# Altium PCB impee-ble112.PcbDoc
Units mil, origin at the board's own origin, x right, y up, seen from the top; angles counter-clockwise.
Board outline 2952.76 x 1968.5 mil, 2 copper layers (Top Layer, Bottom Layer); 26 components, 20 nets, 135 pads, 141 vias.
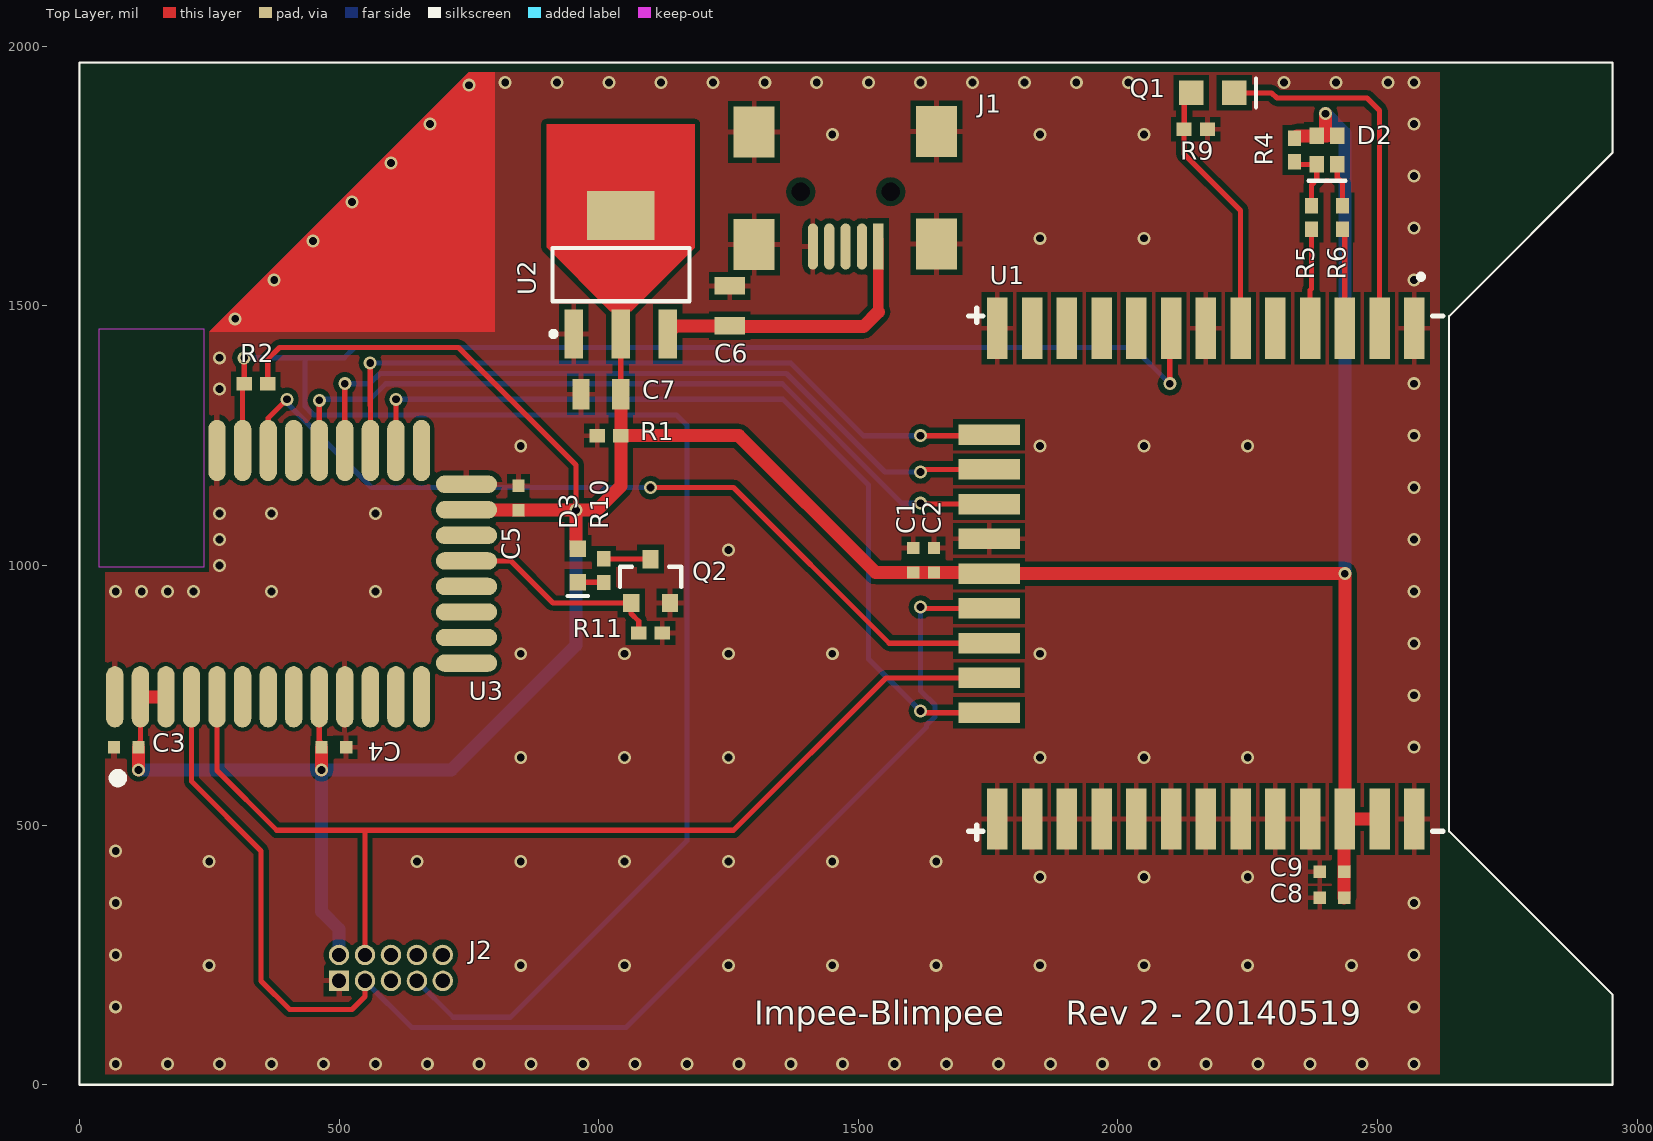
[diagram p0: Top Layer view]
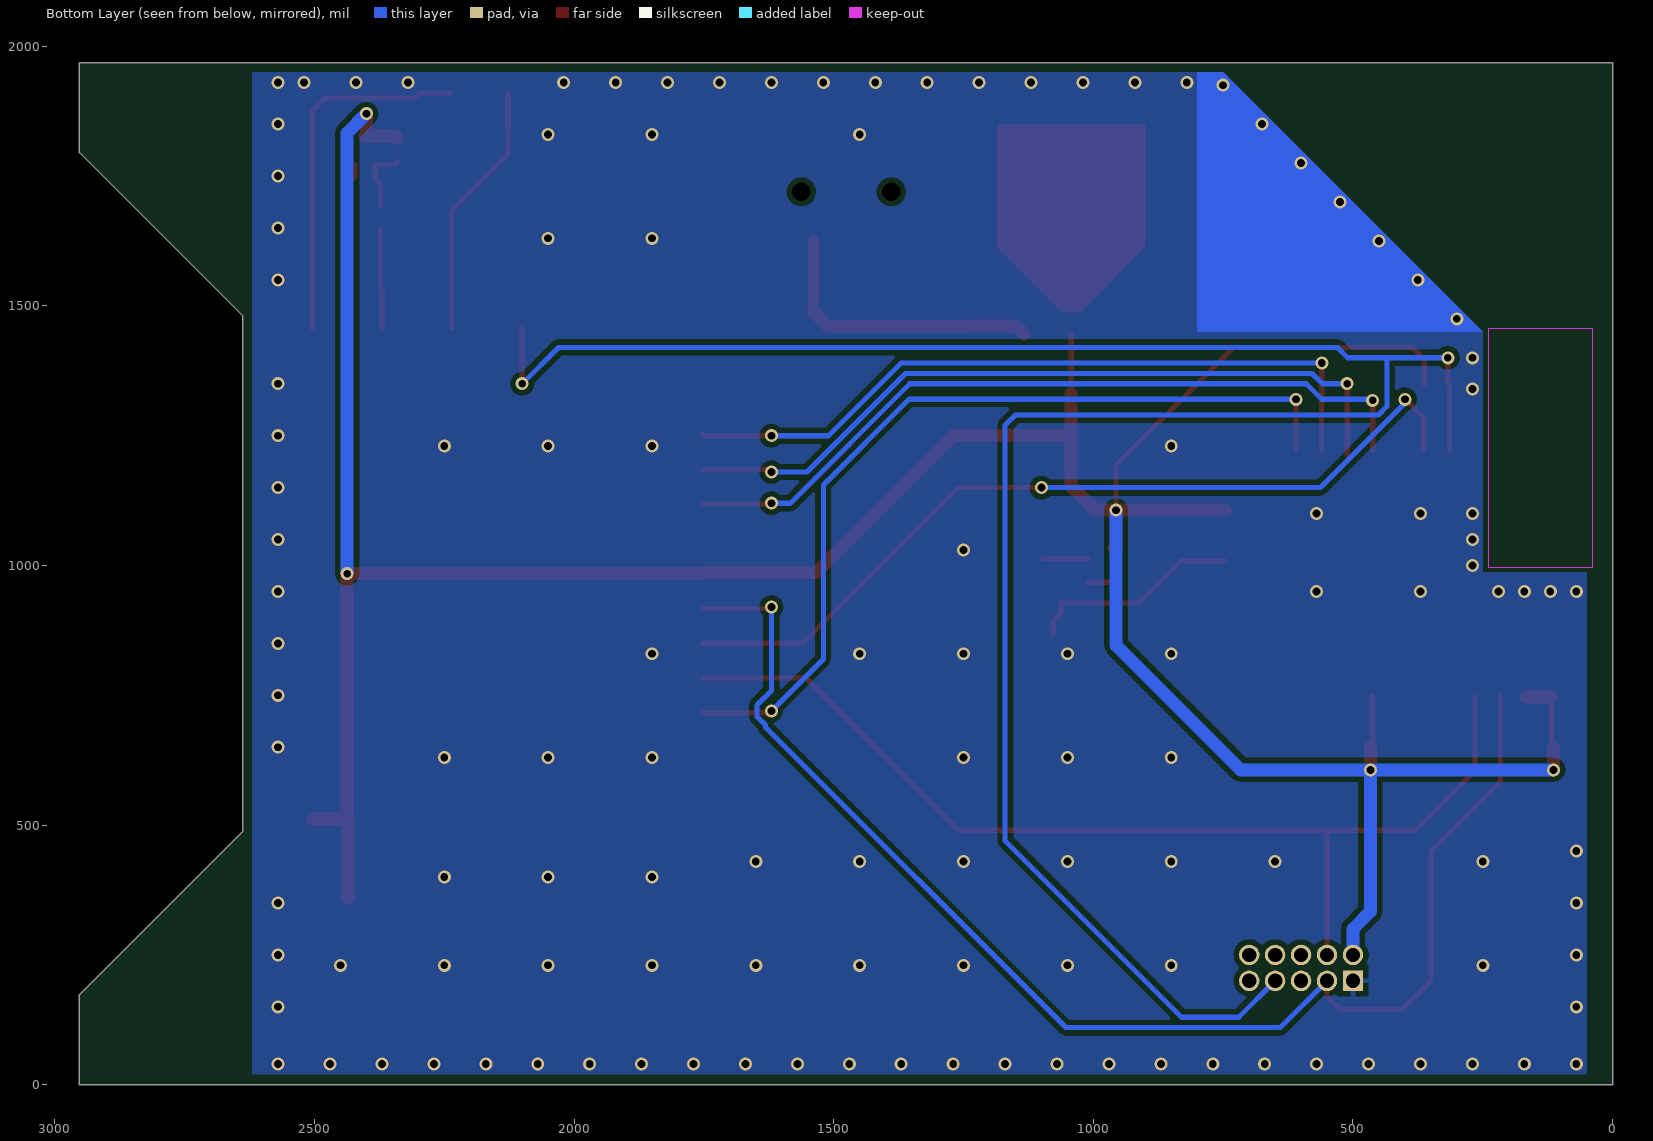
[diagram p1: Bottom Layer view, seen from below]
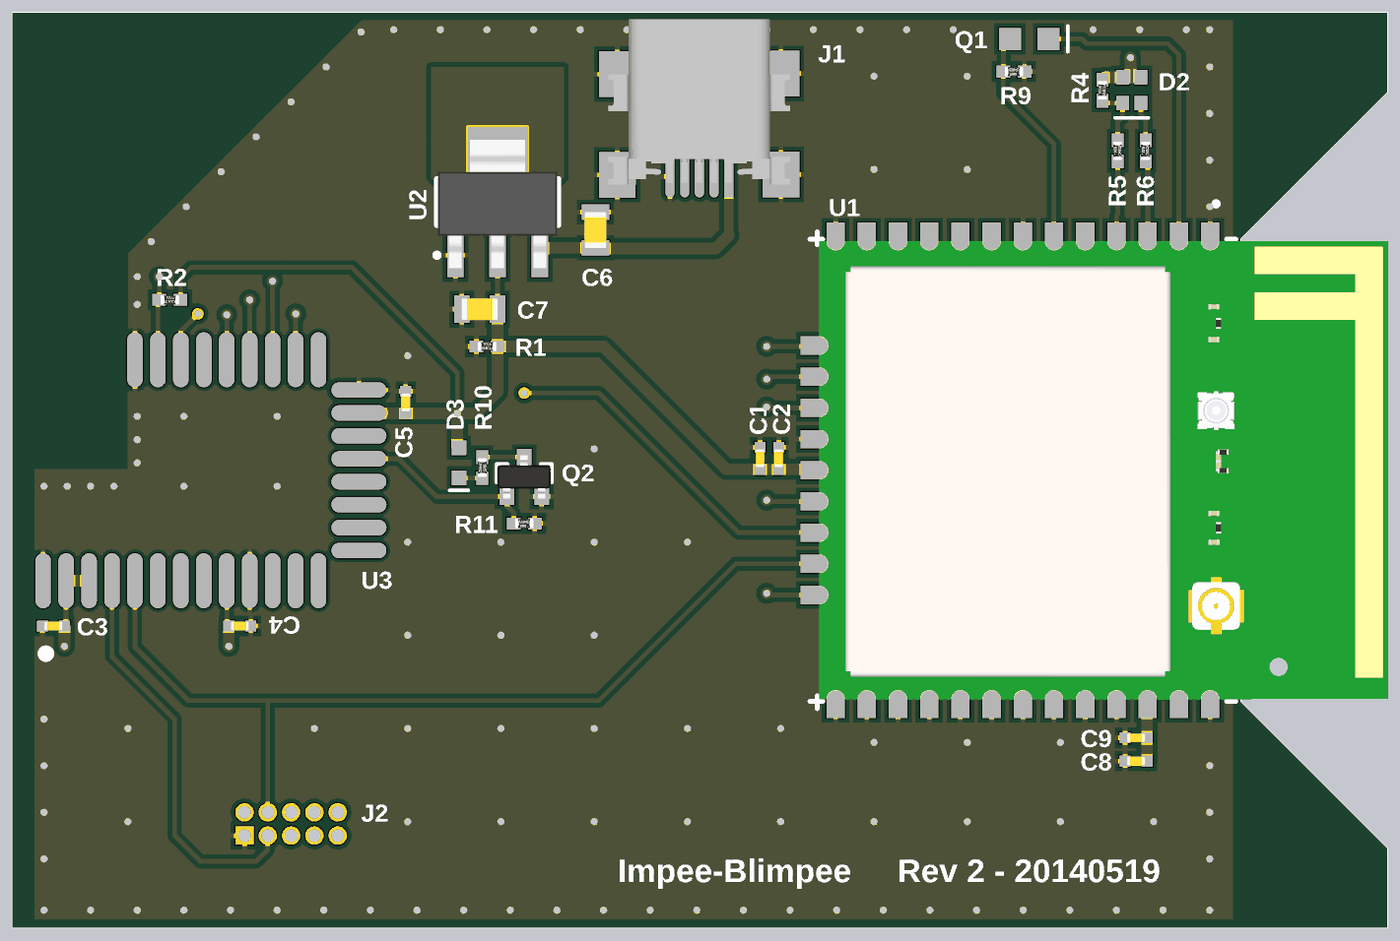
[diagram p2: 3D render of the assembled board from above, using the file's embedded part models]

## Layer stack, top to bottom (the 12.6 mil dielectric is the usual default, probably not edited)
Top Solder: solder mask 0.4, Solder Resist, Dk 3.5
Top Layer: signal copper 1.4
Dielectric 1: dielectric 12.6, FR-4, Dk 4.8
Bottom Layer: signal copper 1.4
Bottom Solder: solder mask 0.4, Solder Resist, Dk 3.5

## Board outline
0,0 0,1968.5 2952.76,1968.5 2952.76,1795.28 2637.8,1480.32 2637.8,488.19 2952.76,173.23 2952.76,0

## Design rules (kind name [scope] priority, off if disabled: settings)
Clearance "PolyRegion Clearance" [IsPad and InComponent('U3') vs IsRegion] p1: gap=8
Clearance [All] p2: gap=10
MinimumSolderMaskSliver [All] p1: minsoldermaskwidth=4
PolygonConnect "Via connect" [isVia] p1: connectstyle=Direct reliefconductorwidth=10 reliefentries=4 polygonreliefangle="90 Angle" airgapwidth=10
PolygonConnect [All] p2: connectstyle=Relief reliefconductorwidth=10 reliefentries=4 polygonreliefangle="90 Angle" airgapwidth=10
RoutingVias [All] p1: holewidth=28 width=50 viastyle="Through Hole" minholewidth=15 minwidth=25 maxholewidth=28 maxwidth=50
SolderMaskExpansion [All] p1: expansion=3
Width [All] p1: maxlimit=25 minlimit=10 preferedwidth=10
28 further rules are at their usual default settings.

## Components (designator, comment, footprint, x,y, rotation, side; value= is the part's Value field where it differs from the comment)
C1 "Ceramic Capacitor" CAPC1005X07N 1605.75,1010 r270 top
C2 "Ceramic Capacitor" CAPC1005X07N 1645.75,1010 r270 top
C3 "Ceramic Capacitor" CAPC1005X07N 90.12,650 r0 top
C4 "Ceramic Capacitor" CAPC1005X07N 490.12,650 r180 top
C5 "Ceramic Capacitor" CAPC1005X07N 845.75,1130 r270 top
C6 "Ceramic Capacitor" CAPC2012X14N 1252.76,1500 r270 top
C7 "Ceramic Capacitor" CAPC2012X14N 1004.37,1330 r0 top
C8 "Ceramic Capacitor" CAPC1005X07N 2412.13,360 r0 top
C9 "Ceramic Capacitor" CAPC1005X07N 2412.13,410 r0 top
D2 "LED Red and Green" LED1616X07N-REDGREEN 2402.76,1800 r90 top
D3 "LED Blue" LED1608X08N-BLUE 960,1000 r90 top
J1 "USB Mini/Micro-B" 4UCON20035 1475.12,1725 r180 top
J2 "Header" HDR127P2X5-N 500,200 r0 top
Q1 "PHOTOTRANSISTOR" PHOTOTRANS2012X13 2182.99,1910.08 r180 top
Q2 "N-Channel MOSFET" SOT95P300X130-3N 1100,970 r90 top
R1 "Resistor" RESC1005X04N 1020.12,1250 r0 top
R2 "Resistor" RESC1005X04N 340,1350 r0 top
R4 "Resistor" RESC1005X04N 2340,1800 r90 top
R5 "Resistor" RESC1005X04N 2372.76,1670 r90 top
R6 "Resistor" RESC1005X04N 2432.76,1670 r90 top
R9 "Resistor" RESC1005X04N 2150,1840 r180 top
R10 "Resistor" RESC1005X04N 1010,990 r270 top
R11 "Resistor" RESC1005X04N 1100,870 r180 top
U1 "imp module" IMP_MODULE 1732.28,1476.38 r270 top locked
U2 "AP1117" SOT230P700X180-4N 1042.76,1560 r90 top
U3 "BLE112" BLE112 389.13,984.25 r90 top

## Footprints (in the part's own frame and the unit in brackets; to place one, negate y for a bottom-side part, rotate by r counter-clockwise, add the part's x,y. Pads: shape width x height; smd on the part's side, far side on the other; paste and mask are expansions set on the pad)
4UCON20035 [mm] "Mini-B USB, Top Mount, Right Angle, SMT"
  rect 0.5x2.25 smd: 1(-1.612,2.813)
  oval 0.5x2.25 smd: 2(-0.812,2.813) 3(-0.012,2.813) 4(0.788,2.813) 5(1.588,2.813)
  round 0 hole 0.9 unplated paste+0 mask+1: H1(-2.213,0.138)
  round 0 hole 0.9 unplated mask+1: H2(2.188,0.138)
  rect 2x2.5 smd: M1(-4.463,2.688) M2(4.463,2.712) M3(-4.463,-2.812) M4(4.463,-2.788)
  body extent -4.95,-5.77 4.95,3.23, height 4.08
BLE112 [mm] "Bluegiga Bluetooth Low Energy Module"
  oval 3x0.85 smd: 1(-6.025,8.15) 2(-6.025,6.9) 3(-6.025,5.65) 4(-6.025,4.4) 5(-6.025,3.15) 6(-6.025,1.9) 7(-6.025,0.65) 8(-6.025,-0.6) 9(-6.025,-1.85) 10(-6.025,-3.1) 11(-6.025,-4.35) 12(-6.025,-5.6) 13(-6.025,-6.85) 22(6.025,-6.85) 23(6.025,-5.6) 24(6.025,-4.35) 25(6.025,-3.1) 26(6.025,-1.85) 27(6.025,-0.6) 28(6.025,0.65) 29(6.025,1.9) 30(6.025,3.15)
  oval 0.85x3 smd: 14(-4.375,-9.05) 15(-3.125,-9.05) 16(-1.875,-9.05) 17(-0.625,-9.05) 18(0.625,-9.05) 19(1.875,-9.05) 20(3.125,-9.05) 21(4.375,-9.05)
  Multi-Layer keep-out region: 0.325,8.9 11.975,8.9 11.975,3.8 0.325,3.8
  silkscreen extent -10.2,7.8 -9.8,8.2, body extent -6.02,-9.05 6.03,9.05, height 2
CAPC1005X07N [mm] "Chip Capacitor, 2-Leads, Body 1.0x0.5mm, IPC Medium Density"
  rect 0.6x0.6 smd: 1(-0.6,0) 2(0.6,0)
  body extent -0.5,-0.25 0.5,0.25, height 0.6
CAPC2012X14N [mm] "Chip Capacitor, 2-Leads, Body 2.0x1.3mm, IPC Medium Density"
  rect 0.85x1.5 smd: 1(-0.975,0) 2(0.975,0)
  body extent -1,-0.6 1,0.6, height 1.4
HDR127P2X5-N [mm] "HDR, 1.27mm Pitch, 2x5-Pin"
  rect 1x1 hole 0.7: 1(0,0)
  round 1 hole 0.7: 2(0,1.27) 3(1.27,0) 4(1.27,1.27) 5(2.54,0) 6(2.54,1.27) 7(3.81,0) 8(3.81,1.27) 9(5.08,0) 10(5.08,1.27)
  body extent -0.63,-1.06 5.72,2.34, height 6.3
IMP_MODULE [mm] "Imp Module, Shadow and Chase"
  rect 3x1 smd: 1(0.5,21.3) 2(0.5,19.6) 3(0.5,17.9) 4(0.5,16.2) 5(0.5,14.5) 6(0.5,12.8) 7(0.5,11.1) 8(0.5,9.4) 9(0.5,7.7) 10(0.5,6) 11(0.5,4.3) 12(0.5,2.6) 13(0.5,0.9) 23(24.5,0.9) 24(24.5,2.6) 25(24.5,4.3) 26(24.5,6) 27(24.5,7.7) 28(24.5,9.4) 29(24.5,11.1) 30(24.5,12.8) 31(24.5,14.5) 32(24.5,16.2) 33(24.5,17.9) 34(24.5,19.6) 35(24.5,21.3)
  rect 1x3 smd: 14(5.7,0.5) 15(7.4,0.5) 16(9.1,0.5) 17(10.8,0.5) 18(12.5,0.5) 19(14.2,0.5) 20(15.9,0.5) 21(17.6,0.5) 22(19.3,0.5)
  silkscreen extent -2.15,-0.5 25.5,22.7, body extent 0,0 25,31, height 1.7
LED1608X08N-BLUE [mm] "LED, 0603 (1608 metric), Blue"
  rect 0.8x0.8 smd: A(0.825,0) K(-0.825,0)
  silkscreen extent -1.5,-0.5 -1.5,0.5, body extent -0.8,-0.4 0.8,0.4, height 0.8
LED1616X07N-REDGREEN [mm] "Bi-Color LED, 0606 (1616 metric), Red, Green"
  rect 0.8x0.7 smd: AG(0.7,-0.5) AR(0.7,0.5) KG(-0.7,-0.5) KR(-0.7,0.5)
  silkscreen extent -1.5,-0.9 -1.5,0.9, body extent -0.8,-0.8 0.8,0.8, height 0.7
PHOTOTRANS2012X13 [mm] "Phototransistor, Top View, 0805 (2012 Metric)"
  rect 1.2x1.2 smd: C(-1.05,0) E(1.05,0)
  silkscreen extent -2.1,-0.7 -2.1,0.7, body extent -1,-0.63 1,0.63, height 1.3
RESC1005X04N [mm] "Chip Resistor, 2-Leads, Body 1.0x0.5mm, IPC Medium Density"
  rect 0.75x0.65 smd: 1(-0.575,0) 2(0.575,0)
  body extent -0.5,-0.25 0.5,0.25, height 0.35
SOT95P300X130-3N [mm] "SOT-23"
  rect 0.9x0.8 smd: 1(-1.075,0.95) 2(-1.075,-0.95) 3(1.075,0)
  silkscreen extent -0.3,-1.5 0.7,1.5, body extent -1.17,-1.45 1.17,1.47, height 1
SOT230P700X180-4N [mm] "SOT223, 4-Leads, Body 6.7x7.3mm (max), Pitch 2.30mm, IPC Medium Density"
  rect 2.4x0.9 smd: 1(-2.9,2.3) 2(-2.9,0) 3(-2.9,-2.3)
  rect 2.4x3.3 smd: 4(2.9,0)
  silkscreen extent -3.02,-3.35 1.3,3.42, body extent -3.6,-3.25 3.4,3.25, height 1.64

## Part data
C1 C9: library part CAPC00043, "CAP,C0G,100pF,5%,50V,0402"
C2 C3 C4 C5 C8: library part CAPC00005, "CAP,X5R,1.0uF,10%,6.3V, 0402,#"
C6: library part CAPC00037, "CAP,X5R,10uF,10%,16V,0805,#"
C7: library part CAPC00039, "CAP,X5R,22uF,10%,6.3V,0805,#"
D2: library part LED00012, "LED, Red and Green, 2/2V, 631/571nm, 25/35mcd, SMT"
D3: library part LED00047, "LED, Blue, 2.8V, 470nm, 15mcd, 0603"
J1: library part USB00001, "USB Mini-B Connector"
J2: library part HDR00025, "HDR, 2x5,1.27mm pitch, Gold Flash, Vertical, THD"
Q1: library part PHOTO00002, "Phototrans, Clear, Top View, 940nm, 0.4V, 1mA, 0805"
Q2: library part NFET00002, "NFET, 60V, 360mA, SOT23"
R1: library part RES00048, "RES,620 Ohm,5%,0.063W,0402"
R2 R11: library part RES00001, "RES,100k,5%,0.063W,0402,#"
R4: library part RES00006, "RES,10k,5%,0.063W,0402,#"
R5 R6 R10: library part RES00024, "RES,100 Ohm,1%,0.063W,0402,#"
R9: library part RES00052, "RES,68K,5%,0.063W,0402#"
U1: library part MOD00002, "Module, Electric Imp Solder Down with Antenna"
U2: library part IC00033, "IC, LDO, Fixed 3.3V, 1A, SOT-223"
U3: library part MOD00011, "Module, BlueGiga BLE112, Bluetooth Low Energy, Built-in Antenna"

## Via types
v1: diameter 25, hole 15, Top Layer to Bottom Layer, tented both sides, 139 vias
v2: diameter 25, hole 15, Top Layer to Bottom Layer, 2 vias

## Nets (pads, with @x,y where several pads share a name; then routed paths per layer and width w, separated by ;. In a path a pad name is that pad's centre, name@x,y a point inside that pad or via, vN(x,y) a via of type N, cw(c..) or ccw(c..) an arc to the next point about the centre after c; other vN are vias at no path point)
3V3: C1.2 C2.2 C3.2 C4.2 C5.2 C7.2 C8.2 C9.2 D2.AG D2.AR D3.A J2.2 R1.2 R2.2 R4.2 U1.18 U1.33 U1.34 U2.2 U2.4 U3.2 U3.3 U3.9 U3.20 | length 6624.4
  Top Layer w10: C3.2 117.48,653.74 U3.2 ; R2.2 362.64,1397.36 385.28,1420 730,1420 956.38,1193.62 v1(956.38,1106.38) ; C4.2@461.97,654.53 U3.9 ; C7.2 U2.2
  Top Layer w25: v1(113.74,606.38) C3.2 ; U3.2 U3.3 ; v1(466.5,606.38) C4.2 ; U3.20 746.34,1106.38 C5.2 v1(956.38,1106.38) ; D3.A 956.38,1032.48 v1(956.38,1106.38) ; C7.2 R1.2 ; R4.2 2344.92,1827.56 D2.AR 2402.76,1827.56 2400,1830.32 v1(2400,1870) ; C8.2 C9.2 2435.75,510.55 U1.33 ; U1.34 U1.33 ; v1(956.38,1106.38) 996.38,1106.38 1042.76,1152.76 R1.2 ; R1.2 1270,1250 1533.62,986.38 C1.2 C2.2 1749.84,986.38 U1.18 v1(2437.01,984.25) U1.33
  Bottom Layer w25: v1(113.74,606.38) v1(466.5,606.38) ; J2.2 500,300 466.5,333.5 v1(466.5,606.38) ; v1(956.38,1106.38) 956.38,846.26 716.5,606.38 v1(466.5,606.38) ; v1(2400,1870) 2437.01,1832.99 v1(2437.01,984.25)
BLE_DC: J2.3 U1.19 U3.4 | length 2606.8
  Top Layer w10: U3.4 215.91,584.5 350,450.4 350,200 405.2,144.8 524.8,144.8 550,170 J2.3 ; v1(1620,920) 1622.68,917.32 U1.19
  Bottom Layer w10: J2.3 640,110 1052.78,110 1631.39,688.61 1631.39,692.5 1647.5,708.61 1647.5,731.39 1620,758.89 v1(1620,920)
BLE_DD: J2.4 U1.21 U3.5 | length 2038.2
  Top Layer w10: U3.5 265.12,604.88 380,490 1260,490 1553.47,783.47 U1.21 ; J2.4 550,490
BLE_IMP_CTS: U1.15 U3.25 | length 1466
  Top Layer w10: U3.25@511.18,1213.82 U3.25 v1(511.18,1350) ; v1(1620,1180) 1625.04,1185.04 U1.15
  Bottom Layer w10: v1(511.18,1350) 558.89,1350 578.89,1370 1361.72,1370 1551.72,1180 v1(1620,1180)
BLE_IMP_RTS: U1.16 U3.26 | length 1499.8
  Top Layer w10: U3.26 v1(461.97,1318.03) ; v1(1620,1120) 1621.89,1118.11 U1.16
  Bottom Layer w10: v1(461.97,1318.03) 460,1320 560,1320 590,1350 1353.43,1350 1583.43,1120 v1(1620,1120)
BLE_IMP_RX: U1.14 U3.24 | length 1419.3
  Top Layer w10: v1(560,1390) U3.24 ; v1(1620,1250) 1750,1250 U1.14
  Bottom Layer w10: v1(560,1390) 570,1390 1370,1390 1510,1250 v1(1620,1250)
BLE_IMP_TX: U1.22 U3.23 | length 1687
  Top Layer w10: U3.23 609.61,1319.61 v1(610,1320) ; v1(1620,720) 1623.46,716.54 U1.22
  Bottom Layer w10: v1(610,1320) 1355.15,1320 1520,1155.15 1520,820 v1(1620,720)
BLE_RESET_L: J2.7 R2.1 U1.8 U3.29 | length 4443.6
  Top Layer w10: U3.29 314.33,1346.97 R2.1 v1(317.36,1400) ; v1(2100,1350) 2100,1454.33 U1.8
  Bottom Layer w10: v1(317.36,1400) 440,1400 ; J2.7 720,130 830,130 1170,470 1170,1270 1150,1290 451.11,1290 434.47,1306.64 434.47,1394.47 440,1400 ; v1(2100,1350) 2030,1420 530,1420 510,1400 440,1400
BLE_WAKE: U1.20 U3.28 | length 1664.3
  Top Layer w10: U3.28 363.54,1283.54 v2(400,1320) ; v2(1100,1150) 1260,1150 1559.61,850.39 U1.20
  Bottom Layer w10: v2(400,1320) 400,1312.83 562.82,1150 v2(1100,1150)
GND: C1.1 C2.1 C3.1 C4.1 C5.1 C6.1 C7.1 C8.1 C9.1 J1.5 J1.M1 J1.M2 J1.M3 J1.M4 J2.1 Q2.2 R1.1 R9.1 R11.1 U1.1 U1.7 U1.13 U1.17 U1.23 U1.24 U1.25 U1.26 U1.27 U1.28 U1.29 U1.30 U1.31 U1.32 U1.35 U2.1 U3.1 U3.10 U3.21 U3.30
  other v1: 70,40 170,40 270,40 370,40 470,40 570,40 670,40 770,40 870,40 970,40 1070,40 1170,40 1270,40 1370,40 1470,40 1570,40 1670,40 1770,40 1870,40 1970,40 2070,40 2170,40 2270,40 2370,40 2470,40 2570,40 70,150 2570,150 250,230 850,230 1050,230 1250,230 1450,230 1650,230 1850,230 2050,230 2250,230 2450,230 70,250 2570,250 70,350 2570,350 1850,400 2050,400 2250,400 250,430 650,430 850,430 1050,430 1250,430 1450,430 1650,430 70,450 850,630 1050,630 1250,630 1850,630 2050,630 2250,630 2570,650 2570,750 850,830 1050,830 1250,830 1450,830 1850,830 2570,850 70,950 120,950 170,950 220,950 370,950 570,950 2570,950 270,1000 1250,1030 270,1050 2570,1050 270,1100 370,1100 570,1100 2570,1150 850,1230 1850,1230 2050,1230 2250,1230 2570,1250 270,1340 2570,1350 270,1400 300.12,1475 375.12,1550 2570,1550 450.12,1625 1850,1630 2050,1630 2570,1650 525.12,1700 2570,1750 600.12,1775 1450,1830 1850,1830 2050,1830 675.12,1850 2570,1850 750.12,1925 820,1930 920,1930 1020,1930 1120,1930 1220,1930 1320,1930 1420,1930 1520,1930 1620,1930 1720,1930 1820,1930 1920,1930 2020,1930 2320,1930 2420,1930 2520,1930 2570,1930
LED_GREEN: R6.1 U1.3 | length 192.4
  Top Layer w10: R6.1 2437.01,1643.11 U1.3
LED_RED: R5.1 U1.4 | length 191.8
  Top Layer w10: U1.4 2370,1456.77 2370,1530 2372.76,1532.76 R5.1
NetD2_KG: D2.KG R6.2 | length 84.1
  Top Layer w10: D2.KG 2422.44,1747.56 2432.76,1737.24 R6.2
NetD2_KR: D2.KR R4.1 R5.2 | length 129.2
  Top Layer w10: R4.1 2344.92,1772.44 D2.KR 2383.07,1743.07 2372.76,1732.76 R5.2
NetD3_K: D3.K R10.2 | length 50.2
  Top Layer w10: D3.K 1010,967.52 R10.2
NetQ2_3: Q2.3 R10.1 | length 90.3
  Top Layer w10: R10.1 1100,1012.64 Q2.3
OPTO_BIAS: Q1.C U1.2 | length 699.3
  Top Layer w10: Q1.C@2238.11,1910.08 2296.06,1910.08 2306.14,1900 2480,1900 2503.94,1876.06 U1.2
OPTO_IN: Q1.E R9.2 U1.6 | length 498.7
  Top Layer w10: Q1.E@2127.87,1910.08 2127.87,1840.51 R9.2 2127.36,1792.64 2236.22,1683.78 U1.6
USER_LED: Q2.1 R11.2 U3.18 | length 414.6
  Top Layer w10: U3.18 831.14,1008.86 912.32,927.68 Q2.1 1062.6,907.4 1077.36,892.64 R11.2
VBUS: C6.2 J1.1 U2.3 | length 562.9
  Top Layer w20: 1538.6,1488.48 J1.1@1538.6,1627.07
  Top Layer w25: U2.3 1149.09,1461.61 C6.2 1254.37,1460 1510.12,1460 1538.6,1488.48
pads on no net: J1.2 J1.3 J1.4 J1.H1 J1.H2 J2.5 J2.6 J2.8 J2.9 J2.10 U1.5 U1.9 U1.10 U1.11 U1.12 U3.6 U3.7 U3.8 U3.11 U3.12 U3.13 U3.14 U3.15 U3.16 U3.17 U3.19 U3.22 U3.27

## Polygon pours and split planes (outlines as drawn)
GND on Top Layer "Top GND" (solid, pour order 3): 50,1950 50,20 2609.88,20 2620,20 2620,1950
GND on Bottom Layer "Bot GND" (solid, remove dead copper, pour order 4): 50,1950 50,20 2609.88,20 2620,20 2620,1950

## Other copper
Top Layer:
  pour cut-out: 249.73,986.85 0,986.85 0,1968.5 250.2,1968.5
  pour cut-out: 799.84,1450 235.02,1450 235.02,1978.5 800.1,1978.5
  region net 3V3: 1062.76,1490 1185,1612.24 1185,1850 900,1850 900,1612.76 1022.76,1490
  region net GND: 750.12,1950 250.12,1450 749.88,1450
  region net GND: 750.12,1950 800.08,1950 799.84,1949.76 799.84,1450 749.88,1450
Bottom Layer:
  pour cut-out: 799.84,1450 235.02,1450 235.02,1978.5 800.1,1978.5
  pour cut-out: 249.73,986.85 0,986.85 0,1968.5 250.2,1968.5
  region net GND: 749.95,1950 249.95,1450 749.71,1450
  region net GND: 749.95,1950 799.91,1950 799.67,1949.76 799.67,1450 749.71,1450

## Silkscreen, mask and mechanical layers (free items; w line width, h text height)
Top Overlay:
  the board outline again, w3.94
  text "Impee-Blimpee" at 1300,100 h80
  text "Rev 2 - 20140519" at 1900,100 h80
Mechanical 6:
  the board outline again, w3.94
Drill Drawing:
  lines w1: 58.12,-712.5 70.62,-712.5 83.12,-725 95.62,-712.5 108.12,-712.5 95.62,-700 108.12,-687.5 95.62,-687.5 83.12,-675 70.62,-687.5 58.12,-687.5 70.62,-700 58.12,-712.5 ; 58.12,-575 108.12,-575 108.12,-525 58.12,-525 58.12,-575 ; 58.12,-375 108.12,-375 83.12,-425 58.12,-375
  lines w15: -10,-770 3868.97,-770 ; -10,-320 3868.97,-320 ; 540.88,-920 540.88,-170 ; 1238.69,-920 1238.69,-170 ; 2584.29,-920 2584.29,-170 ; 3090.17,-920 3090.17,-170 ; -10,-920 3868.97,-920 3868.97,-170 -10,-170 -10,-920
  text "Symbol" at 80,-275 h72
  text "Hit Count" at 585.88,-275 h72
  text "Finished Hole Size" at 1283.69,-275 h72
  text "Plated" at 2629.29,-275 h72
  text "Hole Type" at 3135.17,-275 h72
  text "2" at 585.88,-425 h60
  text "35.43mil (0.900mm)" at 1283.69,-425 h60
  text "NPTH" at 2629.29,-425 h60
  text "Round" at 3135.17,-425 h60
  text "10" at 585.88,-575 h60
  text "27.56mil (0.700mm)" at 1283.69,-575 h60
  text "PTH" at 2629.29,-575 h60
  text "Round" at 3135.17,-575 h60
  text "141" at 585.88,-725 h60
  text "15.00mil (0.381mm)" at 1283.69,-725 h60
  text "PTH" at 2629.29,-725 h60
  text "Round" at 3135.17,-725 h60
  text "153 Total" at 585.88,-875 h60

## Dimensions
0,1970 to 2952.76,1968.5 on Mechanical 1
0,1968.5 to 0,0 on Mechanical 1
